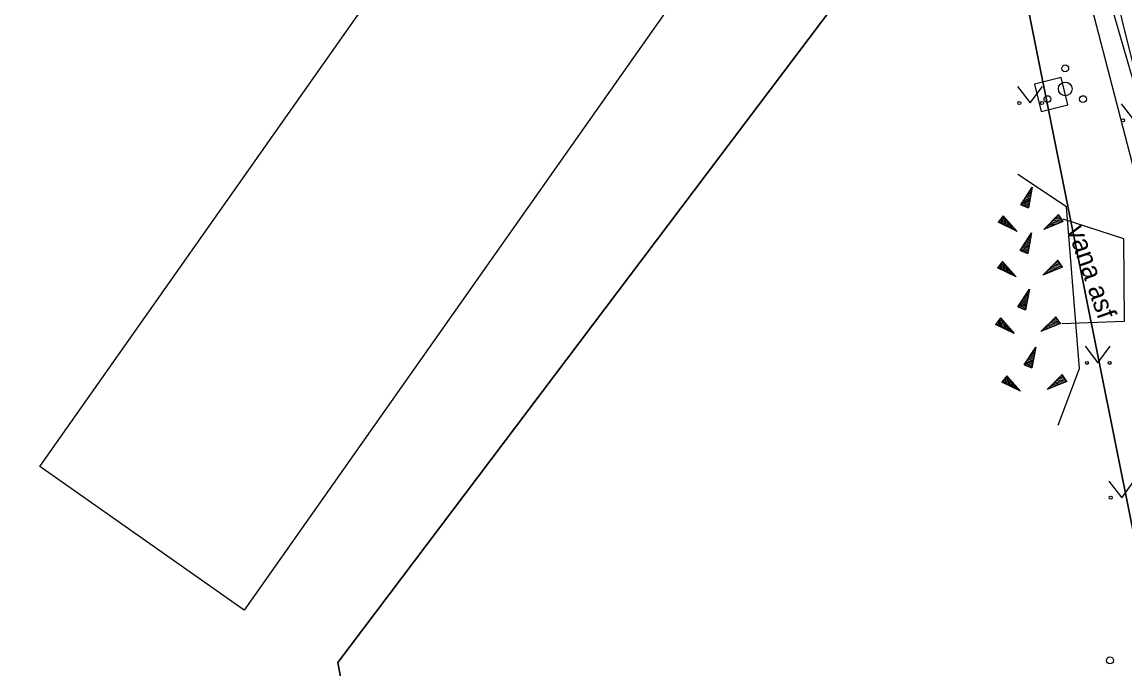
# Model space of a CAD drawing. Extents: x 554947 to 555436, y 6564938 to 6565792.
# Drawn here: x 555307.9 to 555348.19, y 6565480.81 to 6565504.44 of the extents above; entities that cross this region are included whole.
import ezdxf

# ---------------------------------------------------------------- set-up
doc = ezdxf.new("R2010")
doc.units = 0
for name, color, linetype in [('AED', 7, 'Continuous'), ('HALJASTUS', 7, 'Continuous'), ('Hoone Vare', 7, 'Continuous'), ('PIIR', 7, 'Continuous'), ('PR_SIDE', 7, 'Continuous'), ('PUU', 7, 'Continuous'), ('RELJEEF', 7, 'Continuous'), ('TEE', 7, 'Continuous')]:
    doc.layers.add(name, color=color, linetype=linetype)

msp = doc.modelspace()

# ---------------------------------------------------------------- linework, layer by layer
at = {"layer": 'AED'}
msp.add_lwpolyline([(555345.127, 6565501.175), (555346.107, 6565501.417), (555345.861, 6565502.412), (555344.881, 6565502.17)], close=True, dxfattribs=at)
at = {"layer": 'HALJASTUS'}
for p, q in [((555344.266, 6565502.094), (555344.729, 6565501.487)), ((555344.729, 6565501.487), (555345.175, 6565502.094)), ((555348.055, 6565501.461), (555348.518, 6565500.854)), ((555346.736, 6565492.596), (555347.199, 6565491.989)), ((555347.199, 6565491.989), (555347.645, 6565492.596)), ((555347.605, 6565487.672), (555348.068, 6565487.065)), ((555348.068, 6565487.065), (555348.514, 6565487.672))]:
    msp.add_line(p, q, dxfattribs=at)
for centre in [(555344.328, 6565501.487), (555345.157, 6565501.487), (555348.117, 6565500.854), (555346.798, 6565491.989), (555347.627, 6565491.989), (555347.667, 6565487.065)]:
    msp.add_circle(centre, 0.055, dxfattribs=at)
at = {"layer": 'Hoone Vare'}
msp.add_lwpolyline([(555316.008, 6565482.956), (555308.549, 6565488.207), (555330.789, 6565519.787), (555338.249, 6565514.537)], close=True, dxfattribs=at)
at = {"layer": 'PIIR'}
for points in [[(555153.01, 6565448.47), (555161.15, 6565451.45), (555173.66, 6565456.03), (555207.29, 6565506.14), (555287.77, 6565518.56), (555302.6, 6565539.71), (555343.14, 6565512.46), (555319.44, 6565481.04), (555323.07, 6565461.26), (555312.9, 6565433.84), (555316.84, 6565372.52), (555318.72, 6565342.57), (555320.51, 6565314.61), (555303.13, 6565302.54), (555208.78, 6565303.3), (555205.15, 6565297.11), (555200.72, 6565310.3), (555206.9, 6565339.44), (555221.23, 6565376.06), (555216.83, 6565392.35), (555207.22, 6565406.57)], [(555319.44, 6565481.04), (555343.14, 6565512.46), (555351.96, 6565468.55), (555367.06, 6565449.68), (555367.76, 6565374.28), (555361.76, 6565374.07), (555316.84, 6565372.52), (555312.9, 6565433.84), (555323.07, 6565461.26)]]:
    msp.add_lwpolyline(points, close=True, dxfattribs=at)
msp.add_lwpolyline([(555393.069, 6565443.872), (555367.06, 6565449.68), (555351.96, 6565468.55), (555343.14, 6565512.46), (555353.12, 6565523.87), (555358.8, 6565482.45), (555368.05, 6565461.11), (555393.069, 6565454.923)], dxfattribs=at)
at = {"layer": 'PR_SIDE'}
msp.add_lwpolyline([(555383.069, 6565448.914), (555372.326, 6565450.448), (555366.015, 6565452.342), (555363.26, 6565453.626), (555360.292, 6565456.785), (555356.82, 6565461.856), (555354.197, 6565468.745), (555353.746, 6565469.93), (555350.28, 6565487.806), (555348.596, 6565498.754), (555346.199, 6565508), (555346.027, 6565508.326), (555343.44, 6565510.968), (555340.158, 6565515.387), (555337.344, 6565518), (555334.369, 6565519.783), (555331.518, 6565521.47), (555329.521, 6565522.71), (555323.586, 6565526.187), (555323.123, 6565526.49), (555319.055, 6565529.304), (555309.687, 6565535.684), (555309.355, 6565535.944), (555304.351, 6565539.861)], dxfattribs=at)
at = {"layer": 'PUU'}
for centre, radius in [((555346.006, 6565502.752), 0.125), ((555346.006, 6565502.002), 0.25), ((555345.356, 6565501.627), 0.125), ((555346.656, 6565501.627), 0.125), ((555347.639, 6565481.12), 0.125)]:
    msp.add_circle(centre, radius, dxfattribs=at)
at = {"layer": 'RELJEEF'}
for p, q in [((555344.382, 6565497.766), (555344.802, 6565498.406)), ((555344.802, 6565498.406), (555344.662, 6565497.651)), ((555344.482, 6565497.916), (555344.732, 6565498.021)), ((555344.532, 6565497.991), (555344.657, 6565498.046)), ((555344.582, 6565498.066), (555344.752, 6565498.141)), ((555344.632, 6565498.141), (555344.762, 6565498.201)), ((555344.657, 6565498.046), (555344.742, 6565498.081)), ((555344.677, 6565498.216), (555344.777, 6565498.256)), ((555344.727, 6565498.291), (555344.787, 6565498.316)), ((555344.777, 6565498.366), (555344.797, 6565498.376)), ((555344.382, 6565497.766), (555344.707, 6565497.906)), ((555344.382, 6565497.766), (555344.662, 6565497.651)), ((555344.382, 6565497.766), (555344.382, 6565497.766)), ((555344.432, 6565497.841), (555344.717, 6565497.961)), ((555344.447, 6565497.741), (555344.697, 6565497.846)), ((555344.512, 6565497.711), (555344.687, 6565497.786)), ((555344.582, 6565497.686), (555344.677, 6565497.726)), ((555344.647, 6565497.661), (555344.662, 6565497.666)), ((555343.741, 6565497.366), (555343.556, 6565497.126)), ((555343.656, 6565497.256), (555343.681, 6565497.071)), ((555343.696, 6565497.311), (555343.731, 6565497.041)), ((555343.741, 6565497.366), (555344.246, 6565496.796)), ((555343.741, 6565497.366), (555343.786, 6565497.016)), ((555343.741, 6565497.366), (555343.741, 6565497.366)), ((555343.801, 6565497.301), (555343.841, 6565496.991)), ((555343.861, 6565497.231), (555343.896, 6565496.966)), ((555345.22, 6565496.861), (555345.76, 6565497.406)), ((555345.93, 6565497.156), (555345.58, 6565497.221)), ((555345.89, 6565497.211), (555345.625, 6565497.266)), ((555345.85, 6565497.271), (555345.665, 6565497.306)), ((555345.81, 6565497.331), (555345.71, 6565497.351)), ((555345.77, 6565497.391), (555345.75, 6565497.391)), ((555345.93, 6565497.156), (555345.76, 6565497.406)), ((555344.246, 6565496.796), (555343.556, 6565497.126)), ((555343.566, 6565497.141), (555343.571, 6565497.121)), ((555343.611, 6565497.196), (555343.626, 6565497.096)), ((555343.921, 6565497.166), (555343.936, 6565497.026)), ((555343.936, 6565497.026), (555343.951, 6565496.936)), ((555343.976, 6565497.096), (555344.006, 6565496.911)), ((555344.036, 6565497.031), (555344.056, 6565496.886)), ((555344.096, 6565496.961), (555344.111, 6565496.861)), ((555344.156, 6565496.896), (555344.166, 6565496.831)), ((555344.216, 6565496.826), (555344.221, 6565496.806)), ((555345.93, 6565497.156), (555345.22, 6565496.861)), ((555345.26, 6565496.876), (555345.245, 6565496.881)), ((555345.345, 6565496.911), (555345.285, 6565496.926)), ((555345.43, 6565496.946), (555345.325, 6565496.966)), ((555345.51, 6565496.981), (555345.37, 6565497.011)), ((555345.595, 6565497.016), (555345.41, 6565497.051)), ((555345.545, 6565497.076), (555345.455, 6565497.096)), ((555345.76, 6565497.086), (555345.495, 6565497.136)), ((555345.845, 6565497.121), (555345.54, 6565497.181)), ((555345.68, 6565497.051), (555345.545, 6565497.076)), ((555345.93, 6565497.156), (555345.93, 6565497.156)), ((555344.356, 6565496.101), (555344.776, 6565496.741)), ((555344.556, 6565496.401), (555344.726, 6565496.476)), ((555344.606, 6565496.476), (555344.736, 6565496.536)), ((555344.631, 6565496.381), (555344.716, 6565496.416)), ((555344.776, 6565496.741), (555344.636, 6565495.986)), ((555344.651, 6565496.551), (555344.751, 6565496.591)), ((555344.701, 6565496.626), (555344.761, 6565496.651)), ((555344.751, 6565496.701), (555344.771, 6565496.711)), ((555344.356, 6565496.101), (555344.681, 6565496.241)), ((555344.356, 6565496.101), (555344.636, 6565495.986)), ((555344.356, 6565496.101), (555344.356, 6565496.101)), ((555344.406, 6565496.176), (555344.691, 6565496.296)), ((555344.421, 6565496.076), (555344.671, 6565496.181)), ((555344.456, 6565496.251), (555344.706, 6565496.356)), ((555344.486, 6565496.046), (555344.661, 6565496.121)), ((555344.506, 6565496.326), (555344.631, 6565496.381)), ((555344.556, 6565496.021), (555344.651, 6565496.061)), ((555344.621, 6565495.996), (555344.636, 6565496.001)), ((555343.715, 6565495.7), (555343.53, 6565495.46)), ((555343.63, 6565495.59), (555343.655, 6565495.405)), ((555343.67, 6565495.645), (555343.705, 6565495.375)), ((555343.715, 6565495.7), (555344.22, 6565495.13)), ((555343.715, 6565495.7), (555343.76, 6565495.35)), ((555343.715, 6565495.7), (555343.715, 6565495.7)), ((555343.775, 6565495.635), (555343.815, 6565495.325)), ((555345.194, 6565495.195), (555345.734, 6565495.74)), ((555345.864, 6565495.545), (555345.599, 6565495.6)), ((555345.824, 6565495.605), (555345.639, 6565495.64)), ((555345.784, 6565495.665), (555345.684, 6565495.685)), ((555345.744, 6565495.725), (555345.724, 6565495.725)), ((555345.904, 6565495.49), (555345.734, 6565495.74)), ((555344.22, 6565495.13), (555343.53, 6565495.46)), ((555343.54, 6565495.475), (555343.545, 6565495.455)), ((555343.585, 6565495.53), (555343.6, 6565495.43)), ((555343.835, 6565495.565), (555343.87, 6565495.3)), ((555343.895, 6565495.5), (555343.91, 6565495.36)), ((555343.91, 6565495.36), (555343.925, 6565495.27)), ((555343.95, 6565495.43), (555343.98, 6565495.245)), ((555344.01, 6565495.365), (555344.03, 6565495.22)), ((555344.07, 6565495.295), (555344.085, 6565495.195)), ((555344.13, 6565495.23), (555344.14, 6565495.165)), ((555345.904, 6565495.49), (555345.194, 6565495.195)), ((555345.234, 6565495.21), (555345.219, 6565495.215)), ((555345.319, 6565495.245), (555345.259, 6565495.26)), ((555345.404, 6565495.28), (555345.299, 6565495.3)), ((555345.484, 6565495.315), (555345.344, 6565495.345)), ((555345.569, 6565495.35), (555345.384, 6565495.385)), ((555345.519, 6565495.41), (555345.429, 6565495.43)), ((555345.734, 6565495.42), (555345.469, 6565495.47)), ((555345.819, 6565495.455), (555345.514, 6565495.515)), ((555345.654, 6565495.385), (555345.519, 6565495.41)), ((555345.904, 6565495.49), (555345.554, 6565495.555)), ((555345.904, 6565495.49), (555345.904, 6565495.49)), ((555344.19, 6565495.16), (555344.195, 6565495.14)), ((555344.28, 6565494.038), (555344.7, 6565494.678)), ((555344.48, 6565494.338), (555344.65, 6565494.413)), ((555344.53, 6565494.413), (555344.66, 6565494.473)), ((555344.7, 6565494.678), (555344.56, 6565493.923)), ((555344.575, 6565494.488), (555344.675, 6565494.528)), ((555344.625, 6565494.563), (555344.685, 6565494.588)), ((555344.675, 6565494.638), (555344.695, 6565494.648)), ((555344.28, 6565494.038), (555344.605, 6565494.178)), ((555344.28, 6565494.038), (555344.56, 6565493.923)), ((555344.28, 6565494.038), (555344.28, 6565494.038)), ((555344.33, 6565494.113), (555344.615, 6565494.233)), ((555344.345, 6565494.013), (555344.595, 6565494.118)), ((555344.38, 6565494.188), (555344.63, 6565494.293)), ((555344.41, 6565493.983), (555344.585, 6565494.058)), ((555344.43, 6565494.263), (555344.555, 6565494.318)), ((555344.48, 6565493.958), (555344.575, 6565493.998)), ((555344.555, 6565494.318), (555344.64, 6565494.353)), ((555343.639, 6565493.637), (555343.454, 6565493.397)), ((555343.594, 6565493.582), (555343.629, 6565493.312)), ((555343.639, 6565493.637), (555344.144, 6565493.067)), ((555343.639, 6565493.637), (555343.684, 6565493.287)), ((555343.639, 6565493.637), (555343.639, 6565493.637)), ((555343.699, 6565493.572), (555343.739, 6565493.262)), ((555344.545, 6565493.933), (555344.56, 6565493.938)), ((555345.118, 6565493.132), (555345.658, 6565493.677)), ((555345.748, 6565493.542), (555345.563, 6565493.577)), ((555345.708, 6565493.602), (555345.608, 6565493.622)), ((555345.668, 6565493.662), (555345.648, 6565493.662)), ((555345.828, 6565493.427), (555345.658, 6565493.677)), ((555344.144, 6565493.067), (555343.454, 6565493.397)), ((555343.464, 6565493.412), (555343.469, 6565493.392)), ((555343.509, 6565493.467), (555343.524, 6565493.367)), ((555343.554, 6565493.527), (555343.579, 6565493.342)), ((555343.759, 6565493.502), (555343.794, 6565493.237)), ((555343.819, 6565493.437), (555343.834, 6565493.297)), ((555343.834, 6565493.297), (555343.849, 6565493.207)), ((555343.874, 6565493.367), (555343.904, 6565493.182)), ((555343.934, 6565493.302), (555343.954, 6565493.157)), ((555343.994, 6565493.232), (555344.009, 6565493.132)), ((555345.828, 6565493.427), (555345.118, 6565493.132)), ((555345.243, 6565493.182), (555345.183, 6565493.197)), ((555345.328, 6565493.217), (555345.223, 6565493.237)), ((555345.408, 6565493.252), (555345.268, 6565493.282)), ((555345.493, 6565493.287), (555345.308, 6565493.322)), ((555345.443, 6565493.347), (555345.353, 6565493.367)), ((555345.658, 6565493.357), (555345.393, 6565493.407)), ((555345.743, 6565493.392), (555345.438, 6565493.452)), ((555345.578, 6565493.322), (555345.443, 6565493.347)), ((555345.828, 6565493.427), (555345.478, 6565493.492)), ((555345.788, 6565493.482), (555345.523, 6565493.537)), ((555345.828, 6565493.427), (555345.828, 6565493.427)), ((555344.054, 6565493.167), (555344.064, 6565493.102)), ((555344.114, 6565493.097), (555344.119, 6565493.077)), ((555345.158, 6565493.147), (555345.143, 6565493.152)), ((555344.512, 6565491.922), (555344.932, 6565492.562)), ((555344.932, 6565492.562), (555344.792, 6565491.807)), ((555344.807, 6565492.372), (555344.907, 6565492.412)), ((555344.857, 6565492.447), (555344.917, 6565492.472)), ((555344.907, 6565492.522), (555344.927, 6565492.532)), ((555344.512, 6565491.922), (555344.837, 6565492.062)), ((555344.562, 6565491.997), (555344.847, 6565492.117)), ((555344.577, 6565491.897), (555344.827, 6565492.002)), ((555344.612, 6565492.072), (555344.862, 6565492.177)), ((555344.662, 6565492.147), (555344.787, 6565492.202)), ((555344.712, 6565492.222), (555344.882, 6565492.297)), ((555344.762, 6565492.297), (555344.892, 6565492.357)), ((555344.787, 6565492.202), (555344.872, 6565492.237)), ((555344.512, 6565491.922), (555344.792, 6565491.807)), ((555344.512, 6565491.922), (555344.512, 6565491.922)), ((555344.642, 6565491.867), (555344.817, 6565491.942)), ((555344.712, 6565491.842), (555344.807, 6565491.882)), ((555344.777, 6565491.817), (555344.792, 6565491.822)), ((555345.35, 6565491.016), (555345.89, 6565491.561)), ((555346.06, 6565491.311), (555345.89, 6565491.561)), ((555343.871, 6565491.521), (555343.686, 6565491.281)), ((555344.376, 6565490.951), (555343.686, 6565491.281)), ((555343.696, 6565491.296), (555343.701, 6565491.276)), ((555343.741, 6565491.351), (555343.756, 6565491.251)), ((555343.786, 6565491.411), (555343.811, 6565491.226)), ((555343.826, 6565491.466), (555343.861, 6565491.196)), ((555343.871, 6565491.521), (555344.376, 6565490.951)), ((555343.871, 6565491.521), (555343.916, 6565491.171)), ((555343.871, 6565491.521), (555343.871, 6565491.521)), ((555343.931, 6565491.456), (555343.971, 6565491.146)), ((555343.991, 6565491.386), (555344.026, 6565491.121)), ((555344.051, 6565491.321), (555344.066, 6565491.181)), ((555344.066, 6565491.181), (555344.081, 6565491.091)), ((555344.106, 6565491.251), (555344.136, 6565491.066)), ((555344.166, 6565491.186), (555344.186, 6565491.041)), ((555346.06, 6565491.311), (555345.35, 6565491.016)), ((555345.64, 6565491.136), (555345.5, 6565491.166)), ((555345.725, 6565491.171), (555345.54, 6565491.206)), ((555345.675, 6565491.231), (555345.585, 6565491.251)), ((555345.89, 6565491.241), (555345.625, 6565491.291)), ((555345.975, 6565491.276), (555345.67, 6565491.336)), ((555345.81, 6565491.206), (555345.675, 6565491.231)), ((555346.06, 6565491.311), (555345.71, 6565491.376)), ((555346.02, 6565491.366), (555345.755, 6565491.421)), ((555345.98, 6565491.426), (555345.795, 6565491.461)), ((555345.94, 6565491.486), (555345.84, 6565491.506)), ((555345.9, 6565491.546), (555345.88, 6565491.546)), ((555346.06, 6565491.311), (555346.06, 6565491.311)), ((555344.226, 6565491.116), (555344.241, 6565491.016)), ((555344.286, 6565491.051), (555344.296, 6565490.986)), ((555344.346, 6565490.981), (555344.351, 6565490.961)), ((555345.39, 6565491.031), (555345.375, 6565491.036)), ((555345.475, 6565491.066), (555345.415, 6565491.081)), ((555345.56, 6565491.101), (555345.455, 6565491.121))]:
    msp.add_line(p, q, dxfattribs=at)
msp.add_lwpolyline([(555345.748, 6565489.719), (555346.529, 6565491.782), (555346.048, 6565497.69), (555344.278, 6565498.871)], dxfattribs=at)
at = {"layer": 'TEE'}
for points in [[(555393.069, 6565448.493), (555392.904, 6565448.521), (555377.792, 6565450.52), (555372.547, 6565451.424), (555369.187, 6565452.37), (555366.443, 6565453.255), (555364.23, 6565454.662), (555361.13, 6565458.083), (555357.411, 6565463.749), (555354.693, 6565470.258), (555353.748, 6565473.64), (555352.733, 6565478.362), (555351.267, 6565487.961), (555349.516, 6565498.784), (555347.141, 6565508.358), (555345.332, 6565511.802), (555341.773, 6565516.752), (555338.53, 6565519.62), (555330.669, 6565524.333), (555325.029, 6565527.171), (555324.447, 6565527.997), (555320.204, 6565530.941)], [(555349.516, 6565498.784), (555346.789, 6565508.206), (555344.895, 6565511.389), (555341.304, 6565516.362), (555338.53, 6565519.62)], [(555345.917, 6565497.259), (555348.136, 6565496.536), (555348.165, 6565493.505), (555345.883, 6565493.414)]]:
    msp.add_lwpolyline(points, dxfattribs=at)

# ---------------------------------------------------------------- texts
msp.add_text('vana asf', height=0.7, rotation=289.1037, dxfattribs=at).set_placement((555346.069, 6565496.878))

doc.saveas('drawing.dxf')
